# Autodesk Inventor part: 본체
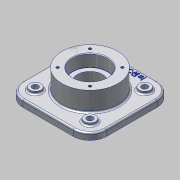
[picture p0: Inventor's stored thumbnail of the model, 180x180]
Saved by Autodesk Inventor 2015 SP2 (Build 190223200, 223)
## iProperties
Created: 2015-07
Part Number: 본체
Material: 알루미늄 6061
Document SubType Name: Modeling
Designer: AMC
Density: 2.7 g/cm^3
Appearance: 알루미늄 - 평지
Author: AMC
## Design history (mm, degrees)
sketch "스케치1"
  geometry: L1 (-75, -75)-(75, -75); L2 (75, -75)-(75, 75); L3 (75, 75)-(-75, 75); L4 (-75, 75)-(-75, -75); L5 (-75, -75)-(75, 75); L6 (75, -75)-(-75, 75); 1 further point
  constraints: 12 end point, 2 midpoint, 2 parallel, 1 horizontal, 1 perpendicular
  dimensions: "d0" = 150 distance of L3.end L2.end; "d1" = 150 distance of L2.end L1.end
extrude "돌출1" new body sketch "스케치1" distance "d2" = 12; taper "d3" = 0 deg
sketch "스케치2"
  geometry: C1 r 50 at (0, 0); 1 further point
  constraints: 1 centre point, 1 coincident
  dimensions: "d4" = 100 diameter of C1
extrude "돌출2" join sketch "스케치2" distance "d5" = 47; taper "d7" = 0 deg; dims "d6" = 23, "d8" = 0
hole "구멍1" diameter "d11" = 45; stored, may be unused: countersink angle "d15" = 90 deg, drill point angle "d17" = 118 deg; dims "d9" = 10, "d10" = 10, "d12" = 6, "d13" = 62, "d14" = 22, "d16" = 9.525
hole "구멍2" diameter "d20" = 45; stored, may be unused: countersink angle "d24" = 90 deg, drill point angle "d26" = 118 deg; dims "d18" = 10, "d19" = 10, "d21" = 6, "d22" = 62, "d23" = 22, "d25" = 9.525
sketch "스케치3"
  geometry: L1 (-49, -49)-(49, -49); L2 (49, -49)-(49, 49); L3 (49, 49)-(-49, 49); L4 (-49, 49)-(-49, -49); L5 (-49, -49)-(49, 49); L6 (49, -49)-(-49, 49); C1 r 10 at (49, 49); C2 r 10 at (49, -49); C3 r 10 at (-49, -49); C4 r 10 at (-49, 49); 1 further point
  constraints: 12 end point, 4 centre point, 4 coincident, 2 midpoint, 2 parallel, 1 horizontal, 1 perpendicular
  dimensions: "d31" = 98 distance of L3.end L2.end; "d32" = 98 distance of L2.end L1.end; "d33" = 20 diameter of C1; "d34" = 20 diameter of C2; "d35" = 20 diameter of C3; "d36" = 20 diameter of C4
extrude "돌출3" join sketch "스케치3" distance "d37" = 5; taper "d38" = 0 deg
hole "구멍3" diameter "d41" = 11; stored, may be unused: countersink angle "d45" = 90 deg, drill point angle "d47" = 118 deg; dims "d39" = 10, "d40" = 10, "d42" = 6, "d43" = 62, "d44" = 22, "d46" = 9.525
hole "구멍4" diameter "d50" = 11; stored, may be unused: countersink angle "d54" = 90 deg, drill point angle "d56" = 118 deg; dims "d48" = 10, "d49" = 10, "d51" = 6, "d52" = 62, "d53" = 22, "d55" = 9.525
hole "구멍5" diameter "d59" = 11; stored, may be unused: countersink angle "d63" = 90 deg, drill point angle "d65" = 118 deg; dims "d57" = 10, "d58" = 10, "d60" = 6, "d61" = 62, "d62" = 22, "d64" = 9.525
hole "구멍6" diameter "d68" = 11; stored, may be unused: countersink angle "d72" = 90 deg, drill point angle "d74" = 118 deg; dims "d66" = 10, "d67" = 10, "d69" = 6, "d70" = 62, "d71" = 22, "d73" = 9.525
sketch "스케치4"
  geometry: L1 (0, 0)-(41, 0); L2 (0, 0)-(28.991, 28.991); L3 (0, 0)-(41, 0); A1 r 41 centre (0, 0) between (41, 0) and (28.991, 28.991); 2 further points
  constraints: 6 end point, 2 coincident, 2 horizontal, 2 point on circle, 1 centre point, 1 equal length
  dimensions: "d75" = 82 diameter of A1; "d76" = 45 deg angle of L3 L2
hole "구멍7" sketch "스케치4" at (28.991, 28.991) diameter "d77" = 4.917; stored, may be unused: countersink angle "d81" = 90 deg, drill point angle "d83" = 118 deg; dims "d78" = 10, "d79" = 62, "d80" = 22, "d82" = 13
sketch "스케치5"
  geometry: L1 (0, 0)-(41, 0); L2 (0, 0)-(28.991, 28.991); L3 (0, 0)-(41, 0); A1 r 41 centre (0, 0) between (41, 0) and (28.991, 28.991); 2 further points
  constraints: 6 end point, 2 coincident, 2 horizontal, 2 point on circle, 1 centre point, 1 equal length
  dimensions: "d87" = 82 diameter of A1; "d88" = 45 deg angle of L3 L2
hole "구멍8" sketch "스케치5" at (28.991, 28.991) diameter "d89" = 4.917; stored, may be unused: countersink angle "d93" = 90 deg, drill point angle "d95" = 118 deg; dims "d90" = 10, "d91" = 62, "d92" = 22, "d94" = 13
sketch "스케치6"
  geometry: 2 further points
  constraints: 1 vertical alignment, 1 other
  dimensions: "d99" = 65 distance of point (0, 0) point (0, 65)
feature "엠보싱1" sketch "스케치6" dims "d0" = 150, "d1" = 150, "d100" = 1, "d101" = 0
fillet "모깎기1" dims "d102" = 30
fillet "모깎기2" dims "d103" = 0.3
chamfer "모따기1" distance "d104" = 1; stored, may be unused: second distance "d105" = 2, angle "d106" = 45 deg
fillet "모깎기3" dims "d107" = 3
fillet "모깎기4" dims "d108" = 3
fillet "모깎기5" dims "d109" = 3
node "솔리드1"
pattern_circular "원형 패턴1" dims angle "d85" = 360 deg
pattern_circular "원형 패턴2" dims angle "d97" = 360 deg
